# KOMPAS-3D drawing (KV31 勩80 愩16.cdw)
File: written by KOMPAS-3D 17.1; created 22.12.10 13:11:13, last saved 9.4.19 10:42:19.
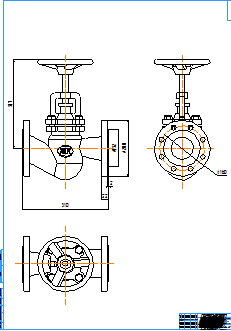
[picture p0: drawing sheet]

Title block, sheet 1: name: KV31 Ду80 Ру16; material: Внимание! Данный продукт является объектом авторского права ООО «Торговый Дом АДЛ». / Запрещается изменение, копирование, распространение / (в том числе путем копирования на другие сайты и ресурсы в Интернете) / или любое иное использование информации и объектов без предварительного / согласия правообладателя (ООО «Торговый Дом АДЛ»).; mass: 27; scale: 1:1; sheets: 1; organisation: ООО "Торговый дом АДЛ"; sheet format: A0; stored path: \\adlc.lan\data\АДЛ_ПКД\3D-модели\ADL production\Вентили ГРАНВЕНТ\KV31\KOMPAS 2D\KV31 Ду80.cdw

Views: Спереди 1, Проекционный вид 2, Вид 5
Dimensions and other numbers on the sheet: 132; 200; 310; 2; 22; 160; 317; 1:1; 1; 27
